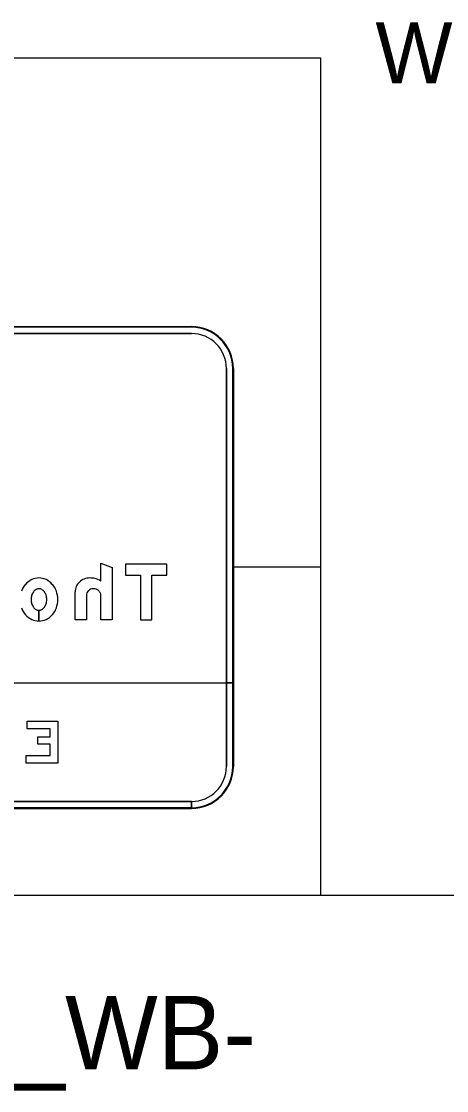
# Model space of a CAD drawing. Extents: x 1726790 to 1728895, y 539219 to 541550.
# Drawn here: x 1727216.6 to 1727265.4, y 541422.6 to 541545.1 of the extents above; entities that cross this region are included whole.
import ezdxf

# ---------------------------------------------------------------- set-up
doc = ezdxf.new("R2010")
doc.units = 0
for name, color, linetype in [('Default', 7, 'Continuous'), ('Old_Level_2', 7, 'Continuous'), ('Typical Pavement Slope Information CELL', 7, 'Continuous'), ('Typical Text Centerline CELL', 7, 'Continuous')]:
    doc.layers.add(name, color=color, linetype=linetype)

msp = doc.modelspace()

# ---------------------------------------------------------------- linework, layer by layer
at = {"layer": 'Default'}
for p, q in [((1727137.33, 541540.92), (1727250.93, 541540.92)), ((1727250.93, 541540.92), (1727250.93, 541445)), ((1727240.93, 541482.6), (1727250.93, 541482.6)), ((1727137.33, 541445), (1727250.93, 541445)), ((1727250.93, 541445), (1727880.5, 541445))]:
    msp.add_line(p, q, dxfattribs=at)
at = {"layer": 'Old_Level_2'}
for p, q in [((1727152.13, 541510.12), (1727236.13, 541510.12)), ((1727152.13, 541510.12), (1727236.13, 541510.12)), ((1727152.13, 541510.12), (1727236.13, 541510.12)), ((1727152.13, 541510.12), (1727236.13, 541510.12)), ((1727152.13, 541510.12), (1727236.13, 541510.12)), ((1727236.13, 541510.04), (1727152.13, 541510.04)), ((1727152.13, 541509.32), (1727236.13, 541509.32)), ((1727236.13, 541509.32), (1727152.13, 541509.32)), ((1727236.13, 541509.32), (1727152.13, 541509.32)), ((1727240.13, 541505.32), (1727240.13, 541459.72)), ((1727240.13, 541459.72), (1727240.13, 541505.32)), ((1727240.13, 541459.72), (1727240.13, 541505.32)), ((1727240.85, 541459.72), (1727240.85, 541505.32)), ((1727240.93, 541505.32), (1727240.93, 541459.72)), ((1727240.93, 541505.32), (1727240.93, 541459.72)), ((1727240.93, 541505.32), (1727240.93, 541459.72)), ((1727240.93, 541505.32), (1727240.93, 541459.72)), ((1727240.93, 541505.32), (1727240.93, 541459.72)), ((1727218.64, 541476.39), (1727218.64, 541477.62)), ((1727218.64, 541477.62), (1727218.64, 541476.39)), ((1727218.64, 541476.39), (1727218.64, 541477.62)), ((1727218.64, 541477.62), (1727218.64, 541476.39)), ((1727147.33, 541469.32), (1727240.93, 541469.32)), ((1727147.33, 541469.32), (1727240.93, 541469.32)), ((1727147.33, 541469.32), (1727240.93, 541469.32)), ((1727240.93, 541469.32), (1727240.13, 541469.32)), ((1727240.13, 541469.32), (1727240.13, 541468.52)), ((1727240.93, 541469.32), (1727240.13, 541469.32)), ((1727240.13, 541469.32), (1727240.13, 541468.52)), ((1727240.93, 541469.32), (1727240.13, 541469.32)), ((1727240.13, 541469.32), (1727240.13, 541468.52)), ((1727240.93, 541469.32), (1727240.85, 541469.32)), ((1727240.85, 541469.32), (1727240.85, 541469.24)), ((1727240.85, 541469.24), (1727240.85, 541459.72)), ((1727240.93, 541469.32), (1727240.93, 541459.72)), ((1727240.93, 541459.72), (1727240.93, 541469.32)), ((1727240.93, 541459.72), (1727240.93, 541469.32)), ((1727240.93, 541459.72), (1727240.93, 541469.32)), ((1727240.93, 541469.32), (1727240.93, 541459.72)), ((1727240.93, 541469.32), (1727240.93, 541459.72)), ((1727240.93, 541459.72), (1727240.93, 541469.32)), ((1727240.13, 541468.52), (1727240.13, 541459.72)), ((1727240.13, 541468.52), (1727240.13, 541459.72)), ((1727240.13, 541468.52), (1727240.13, 541459.72)), ((1727236.13, 541455.72), (1727152.13, 541455.72)), ((1727236.13, 541455.72), (1727152.13, 541455.72)), ((1727236.13, 541455.72), (1727152.13, 541455.72)), ((1727236.13, 541455.72), (1727152.13, 541455.72)), ((1727152.13, 541455.72), (1727236.12, 541455.72)), ((1727152.13, 541455.72), (1727236.12, 541455.72)), ((1727236.12, 541455.72), (1727236.12, 541454.92)), ((1727236.12, 541455.72), (1727236.12, 541454.92)), ((1727236.13, 541454.92), (1727236.13, 541455.72)), ((1727236.13, 541454.92), (1727236.13, 541455.72)), ((1727236.13, 541455), (1727152.13, 541455)), ((1727152.13, 541455), (1727236.13, 541455)), ((1727236.13, 541454.92), (1727152.13, 541454.92)), ((1727152.13, 541454.92), (1727236.13, 541454.92)), ((1727152.13, 541454.92), (1727236.13, 541454.92)), ((1727152.13, 541454.92), (1727236.13, 541454.92)), ((1727236.13, 541454.92), (1727152.13, 541454.92)), ((1727236.13, 541454.92), (1727152.13, 541454.92)), ((1727152.13, 541454.92), (1727236.13, 541454.92)), ((1727236.13, 541454.92), (1727152.13, 541454.92)), ((1727236.13, 541454.92), (1727152.13, 541454.92)), ((1727236.12, 541454.92), (1727152.13, 541454.92)), ((1727236.12, 541454.92), (1727152.13, 541454.92)), ((1727236.13, 541454.92), (1727152.13, 541454.92)), ((1727236.13, 541454.92), (1727236.13, 541455)), ((1727236.13, 541455), (1727236.13, 541454.92))]:
    msp.add_line(p, q, dxfattribs=at)
for points in [[(1727225.74, 541480.96), (1727225.74, 541483.03), (1727227.02, 541482.54), (1727227.02, 541476.52), (1727225.74, 541476.52), (1727225.74, 541479.33)], [(1727225.74, 541480.96), (1727225.74, 541483.03), (1727227.02, 541482.54), (1727227.02, 541476.52), (1727225.74, 541476.52), (1727225.74, 541479.33)], [(1727225.74, 541480.96), (1727225.74, 541483.03), (1727227.02, 541482.54), (1727227.02, 541476.52), (1727225.74, 541476.52), (1727225.74, 541479.33)], [(1727224.08, 541479.33), (1727224.08, 541476.52), (1727222.8, 541476.52), (1727222.8, 541479.75)], [(1727224.08, 541479.33), (1727224.08, 541476.52), (1727222.8, 541476.52), (1727222.8, 541479.75)], [(1727224.08, 541479.33), (1727224.08, 541476.52), (1727222.8, 541476.52), (1727222.8, 541479.75)]]:
    msp.add_lwpolyline(points, dxfattribs=at)
for points in [[(1727230.29, 541476.52), (1727231.57, 541476.52), (1727231.57, 541481.64), (1727233.29, 541481.64), (1727233.29, 541482.92), (1727228.56, 541482.92), (1727228.56, 541481.64), (1727230.29, 541481.64)], [(1727230.29, 541476.52), (1727231.57, 541476.52), (1727231.57, 541481.64), (1727233.29, 541481.64), (1727233.29, 541482.92), (1727228.56, 541482.92), (1727228.56, 541481.64), (1727230.29, 541481.64)], [(1727230.29, 541476.52), (1727231.57, 541476.52), (1727231.57, 541481.64), (1727233.29, 541481.64), (1727233.29, 541482.92), (1727228.56, 541482.92), (1727228.56, 541481.64), (1727230.29, 541481.64)], [(1727217.2, 541460.98), (1727219.94, 541460.98), (1727219.94, 541462.27), (1727218.52, 541462.27), (1727218.52, 541463.14), (1727219.94, 541463.14), (1727219.94, 541464.05), (1727217.28, 541464.05), (1727217.28, 541464.92), (1727220.8, 541464.92), (1727220.8, 541460.12), (1727217.2, 541460.12)], [(1727217.2, 541460.98), (1727219.94, 541460.98), (1727219.94, 541462.27), (1727218.52, 541462.27), (1727218.52, 541463.14), (1727219.94, 541463.14), (1727219.94, 541464.05), (1727217.28, 541464.05), (1727217.28, 541464.92), (1727220.8, 541464.92), (1727220.8, 541460.12), (1727217.2, 541460.12)], [(1727217.2, 541460.98), (1727219.94, 541460.98), (1727219.94, 541462.27), (1727218.52, 541462.27), (1727218.52, 541463.14), (1727219.94, 541463.14), (1727219.94, 541464.05), (1727217.28, 541464.05), (1727217.28, 541464.92), (1727220.8, 541464.92), (1727220.8, 541460.12), (1727217.2, 541460.12)]]:
    msp.add_lwpolyline(points, close=True, dxfattribs=at)
for centre, radius, start, end in [((1727236.13, 541505.32), 4.8, 0, 90), ((1727236.13, 541505.32), 4.8, 0, 90), ((1727236.13, 541505.32), 4.8, 0, 90), ((1727236.13, 541505.32), 4.8, 0, 90), ((1727236.13, 541505.32), 4.8, 0, 90), ((1727236.13, 541505.32), 4.72, 0, 90), ((1727236.13, 541505.32), 4, 0, 90), ((1727236.13, 541505.32), 4, 0, 90), ((1727236.13, 541505.32), 4, 0, 90), ((1727224.27, 541479.75), 1.47, 156.0683, 180), ((1727224.27, 541479.75), 1.47, 156.0683, 180), ((1727224.27, 541479.75), 1.47, 156.0683, 180), ((1727224.37, 541479.7), 1.58, 133.025, 156.0683), ((1727224.37, 541479.7), 1.58, 133.025, 156.0683), ((1727224.37, 541479.7), 1.58, 133.025, 156.0683), ((1727224.44, 541479.63), 1.68, 111.1364, 133.025), ((1727224.44, 541479.63), 1.68, 111.1364, 133.025), ((1727224.44, 541479.63), 1.68, 111.1364, 133.025), ((1727224.48, 541479.52), 1.8, 90, 111.1364), ((1727224.48, 541479.52), 1.8, 90, 111.1364), ((1727224.48, 541479.52), 1.8, 90, 111.1364), ((1727224.48, 541478.76), 2.56, 77.3957, 90), ((1727224.48, 541478.76), 2.56, 77.3957, 90), ((1727224.48, 541478.76), 2.56, 77.3957, 90), ((1727224.5, 541479.02), 2.3, 57.5057, 76.5305), ((1727224.5, 541479.02), 2.3, 57.5057, 76.5305), ((1727224.5, 541479.02), 2.3, 57.5057, 76.5305), ((1727224.82, 541479.33), 0.742, 156.9072, 180), ((1727224.82, 541479.33), 0.742, 156.9072, 180), ((1727224.82, 541479.33), 0.742, 156.9072, 180), ((1727224.84, 541479.32), 0.765, 134.1702, 156.9072), ((1727224.84, 541479.32), 0.765, 134.1702, 156.9072), ((1727224.84, 541479.32), 0.765, 134.1702, 156.9072), ((1727224.86, 541479.3), 0.785, 111.9192, 134.1702), ((1727224.86, 541479.3), 0.785, 111.9192, 134.1702), ((1727224.86, 541479.3), 0.785, 111.9192, 134.1702), ((1727224.86, 541479.28), 0.809, 90, 111.9192), ((1727224.86, 541479.28), 0.809, 90, 111.9192), ((1727224.86, 541479.28), 0.809, 90, 111.9192), ((1727224.86, 541479.08), 1.01, 70.1926, 90), ((1727224.86, 541479.08), 1.01, 70.1926, 90), ((1727224.86, 541479.08), 1.01, 70.1926, 90), ((1727224.91, 541479.2), 0.881, 48.9924, 70.1926), ((1727224.91, 541479.2), 0.881, 48.9924, 70.1926), ((1727224.91, 541479.2), 0.881, 48.9924, 70.1926), ((1727224.97, 541479.28), 0.78, 25.4717, 48.9924), ((1727224.97, 541479.28), 0.78, 25.4717, 48.9924), ((1727224.97, 541479.28), 0.78, 25.4717, 48.9924), ((1727225.08, 541479.33), 0.667, 0, 25.4717), ((1727225.08, 541479.33), 0.667, 0, 25.4717), ((1727225.08, 541479.33), 0.667, 0, 25.4717), ((1727236.13, 541459.72), 4.8, 270, 0), ((1727236.13, 541459.72), 4.8, 270, 0), ((1727236.13, 541459.72), 4, 270, 0), ((1727236.13, 541459.72), 4.8, 270, 0), ((1727236.13, 541459.72), 4, 270, 0), ((1727236.13, 541459.72), 4.8, 270, 0), ((1727236.13, 541459.72), 4, 270, 0), ((1727236.13, 541459.72), 4.8, 270, 0), ((1727236.13, 541459.72), 4.8, 270, 0), ((1727236.13, 541459.72), 4.8, 270, 0), ((1727236.13, 541459.72), 4.72, 270, 0), ((1727236.13, 541459.72), 4.8, 270, 0), ((1727236.13, 541459.72), 4.8, 270, 0), ((1727236.13, 541459.72), 4, 270, 0), ((1727236.13, 541459.72), 4.8, 270, 0), ((1727236.13, 541459.72), 4, 270, 0), ((1727236.13, 541459.72), 4.8, 270, 0), ((1727236.13, 541459.72), 4, 270, 0), ((1727236.13, 541459.72), 4.8, 270, 0), ((1727236.13, 541459.72), 4.72, 270, 0)]:
    msp.add_arc(centre, radius, start, end, dxfattribs=at)
for centre, major_axis, start_param, end_param in [((1727218.95, 541478.96), (0, -2.47), 3.98898, 4.361709), ((1727218.95, 541478.96), (0, -2.47), 3.98898, 4.361709), ((1727218.95, 541478.96), (0, -2.47), 3.98898, 4.361709), ((1727218.76, 541479.13), (0, -2.21), 3.580164, 3.98898), ((1727218.76, 541479.13), (0, -2.21), 3.580164, 3.98898), ((1727218.76, 541479.13), (0, -2.21), 3.580164, 3.98898), ((1727218.64, 541479.39), (0, -1.93), 3.141593, 3.580164), ((1727218.64, 541479.39), (0, -1.93), 3.141593, 3.580164), ((1727218.64, 541479.39), (0, -1.93), 3.141593, 3.580164), ((1727218.64, 541479.39), (0, -1.93), 2.703022, 3.141593), ((1727218.64, 541479.39), (0, -1.93), 2.703022, 3.141593), ((1727218.64, 541479.39), (0, -1.93), 2.703022, 3.141593), ((1727218.52, 541479.13), (0, -2.21), 2.294205, 2.703022), ((1727218.52, 541479.13), (0, -2.21), 2.294205, 2.703022), ((1727218.52, 541479.13), (0, -2.21), 2.294205, 2.703022), ((1727218.33, 541478.96), (0, -2.47), 1.921476, 2.294205), ((1727218.33, 541478.96), (0, -2.47), 1.921476, 2.294205), ((1727218.33, 541478.96), (0, -2.47), 1.921476, 2.294205), ((1727219.43, 541478.85), (0, -1.69), 4.419789, 4.712389), ((1727219.43, 541478.85), (0, -1.69), 4.419789, 4.712389), ((1727219.43, 541478.85), (0, -1.69), 4.419789, 4.712389), ((1727219.04, 541478.97), (0, -1.28), 4.083593, 4.419789), ((1727219.04, 541478.97), (0, -1.28), 4.083593, 4.419789), ((1727219.04, 541478.97), (0, -1.28), 4.083593, 4.419789), ((1727218.8, 541479.15), (0, -0.977), 3.659317, 4.083593), ((1727218.8, 541479.15), (0, -0.977), 3.659317, 4.083593), ((1727218.8, 541479.15), (0, -0.977), 3.659317, 4.083593), ((1727218.64, 541479.43), (0, -0.661), 3.141593, 3.659317), ((1727218.64, 541479.43), (0, -0.661), 3.141593, 3.659317), ((1727218.64, 541479.43), (0, -0.661), 3.141593, 3.659317), ((1727218.64, 541479.43), (0, -0.661), 2.623869, 3.141593), ((1727218.64, 541479.43), (0, -0.661), 2.623869, 3.141593), ((1727218.64, 541479.43), (0, -0.661), 2.623869, 3.141593), ((1727218.48, 541479.15), (0, -0.977), 2.199593, 2.623869), ((1727218.48, 541479.15), (0, -0.977), 2.199593, 2.623869), ((1727218.48, 541479.15), (0, -0.977), 2.199593, 2.623869), ((1727218.24, 541478.97), (0, -1.28), 1.863396, 2.199593), ((1727218.24, 541478.97), (0, -1.28), 1.863396, 2.199593), ((1727218.24, 541478.97), (0, -1.28), 1.863396, 2.199593), ((1727217.85, 541478.85), (0, -1.69), 1.570796, 1.863396), ((1727217.85, 541478.85), (0, -1.69), 1.570796, 1.863396), ((1727217.85, 541478.85), (0, -1.69), 1.570796, 1.863396), ((1727218.03, 541478.85), (0, -2.78), 1.570796, 1.921476), ((1727218.03, 541478.85), (0, -2.78), 1.570796, 1.921476), ((1727218.03, 541478.85), (0, -2.78), 1.570796, 1.921476), ((1727218.95, 541478.75), (0, -2.47), 5.063069, 5.435798), ((1727218.95, 541478.75), (0, -2.47), 5.063069, 5.435798), ((1727218.95, 541478.75), (0, -2.47), 5.063069, 5.435798), ((1727219.43, 541478.85), (0, -1.69), 4.712389, 5.004989), ((1727219.43, 541478.85), (0, -1.69), 4.712389, 5.004989), ((1727219.43, 541478.85), (0, -1.69), 4.712389, 5.004989), ((1727219.04, 541478.74), (0, -1.28), 5.004989, 5.341185), ((1727219.04, 541478.74), (0, -1.28), 5.004989, 5.341185), ((1727219.04, 541478.74), (0, -1.28), 5.004989, 5.341185), ((1727218.8, 541478.56), (0, -0.977), 5.341185, 5.765461), ((1727218.8, 541478.56), (0, -0.977), 5.341185, 5.765461), ((1727218.8, 541478.56), (0, -0.977), 5.341185, 5.765461), ((1727218.48, 541478.56), (0, -0.977), 0.517724, 0.942), ((1727218.48, 541478.56), (0, -0.977), 0.517724, 0.942), ((1727218.48, 541478.56), (0, -0.977), 0.517724, 0.942), ((1727218.24, 541478.74), (0, -1.28), 0.942, 1.278197), ((1727218.24, 541478.74), (0, -1.28), 0.942, 1.278197), ((1727218.24, 541478.74), (0, -1.28), 0.942, 1.278197), ((1727217.85, 541478.85), (0, -1.69), 1.278197, 1.570796), ((1727217.85, 541478.85), (0, -1.69), 1.278197, 1.570796), ((1727217.85, 541478.85), (0, -1.69), 1.278197, 1.570796), ((1727218.33, 541478.75), (0, -2.47), 0.847388, 1.220117), ((1727218.33, 541478.75), (0, -2.47), 0.847388, 1.220117), ((1727218.33, 541478.75), (0, -2.47), 0.847388, 1.220117), ((1727218.03, 541478.85), (0, -2.78), 1.220117, 1.570796), ((1727218.03, 541478.85), (0, -2.78), 1.220117, 1.570796), ((1727218.03, 541478.85), (0, -2.78), 1.220117, 1.570796), ((1727218.76, 541478.58), (0, -2.21), 5.435798, 5.844614), ((1727218.76, 541478.58), (0, -2.21), 5.435798, 5.844614), ((1727218.76, 541478.58), (0, -2.21), 5.435798, 5.844614), ((1727218.64, 541478.32), (0, -1.93), 5.844614, 6.283185), ((1727218.64, 541478.32), (0, -1.93), 5.844614, 6.283019), ((1727218.64, 541478.32), (0, -1.93), 5.844614, 6.283019), ((1727218.64, 541478.28), (0, -0.661), 5.765461, 6.283185), ((1727218.64, 541478.28), (0, -0.661), 5.765461, 6.282701), ((1727218.64, 541478.28), (0, -0.661), 5.765461, 6.282701), ((1727218.64, 541478.28), (0, -0.661), 0, 0.517724), ((1727218.64, 541478.28), (0, -0.661), 0, 0.517724), ((1727218.64, 541478.28), (0, -0.661), 0, 0.517724), ((1727218.64, 541478.32), (0, -1.93), 6.283185, 6.721756), ((1727218.64, 541478.32), (0, -1.93), 0, 0.438571), ((1727218.64, 541478.32), (0, -1.93), 0, 0.438571), ((1727218.52, 541478.58), (0, -2.21), 0.438571, 0.847388), ((1727218.52, 541478.58), (0, -2.21), 0.438571, 0.847388), ((1727218.52, 541478.58), (0, -2.21), 0.438571, 0.847388)]:
    msp.add_ellipse(centre, major_axis=major_axis, ratio=0.999993, start_param=start_param, end_param=end_param, dxfattribs=at)

# ---------------------------------------------------------------- texts
at = {"layer": 'Typical Pavement Slope Information CELL'}
msp.add_text('WINDLOAD AREA: 282" X 234"', height=7.0055, dxfattribs=at).set_placement((1727257.21, 541537.98))
at = {"layer": 'Typical Text Centerline CELL'}
msp.add_text('-L_WB-', height=8.421, dxfattribs=at).set_placement((1727205.36, 541425.03))

doc.saveas('drawing.dxf')
